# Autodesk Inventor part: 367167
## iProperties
Created: 2006-08
Part Number: 367167
Material: 12.9
Description: Zylinderschraube
Vendor: Autodesk Inc.
Document SubType Name: Modeling
Standard: DIN 912
Designer: I.Baliuc
Standards Organization: DIN
Language: de-DE
Size Designation: M6 x 25
Categories: <MemberInstance Version="R10.0.0"><Categories><Category DisplayName="Schrauben" InternalName="e4da775c-781d-43d5-af7c-5136215cf5a6" Mnemonic="FSTN"><Category Di
Density: 7.85 g/cm^3
Mass: 8.58266 g
Surface Area: 8.59153 cm^2
Volume: 1.09333 cm^3
Abmessung: M6 x 25
Author: T.Messerschmitt
Comments: DIN 912 - M6 x 25
Revision Number: 367167
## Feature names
1. Körper [Revolution]
2. Loch [Extrusion]
3. Rundung1 [Fillet]
4. Fase1 [Chamfer]
